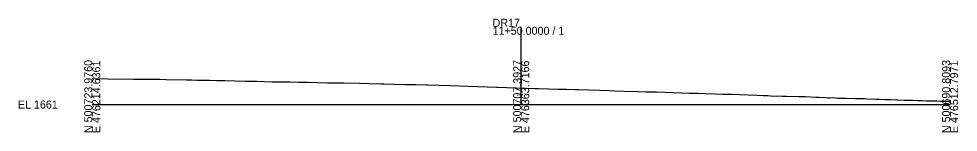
# Model space of a CAD drawing. Extents: x -26 to 303, y -96 to 3030.
# Drawn here: x -25.7 to 302.8, y 2990.3 to 3030 of the extents above; entities that cross this region are included whole.
import ezdxf

# ---------------------------------------------------------------- set-up
doc = ezdxf.new("R2010")
doc.units = 0
for name, color, linetype in [('Exist Cross Section Cell', 7, 'Continuous'), ('Exist XS Center Line Elevation Label', 7, 'Continuous'), ('Exist XS Ground Line', 7, 'Continuous')]:
    doc.layers.add(name, color=color, linetype=linetype)

msp = doc.modelspace()

# ---------------------------------------------------------------- linework, layer by layer
at = {"layer": 'Exist Cross Section Cell'}
for p, q in [((150, 3000), (150, 3027.23)), ((0, 3000), (150, 3000)), ((150, 3000), (300, 3000))]:
    msp.add_line(p, q, dxfattribs=at)
at = {"layer": 'Exist XS Ground Line'}
msp.add_lwpolyline([(0, 3009.08), (5.42, 3009.04), (14.44, 3008.94), (17.43, 3008.89), (18.58, 3008.93), (21.6, 3008.88), (23.69, 3008.84), (25.74, 3008.8), (32.91, 3008.64), (34.73, 3008.61), (36.63, 3008.57), (38.68, 3008.52), (40.97, 3008.48), (43.55, 3008.44), (46.37, 3008.39), (53.54, 3008.2), (57.51, 3008.14), (60.23, 3008.08), (62.98, 3008.01), (65.85, 3007.94), (69.15, 3007.9), (72.13, 3007.84), (75.27, 3007.78), (78.62, 3007.73), (82.26, 3007.66), (84.39, 3007.62), (88.03, 3007.56), (93.43, 3007.44), (97.12, 3007.36), (100.91, 3007.28), (101.96, 3007.26), (105.6, 3007.17), (109.26, 3007.07), (113.01, 3006.97), (116.9, 3006.88), (117.35, 3006.86), (121.31, 3006.76), (125.39, 3006.63), (131.34, 3006.42), (134.85, 3006.29), (138.16, 3006.17), (141.33, 3006.07), (141.73, 3006.05), (144.97, 3005.94), (148.21, 3005.83), (150, 3005.77), (151.53, 3005.72), (154.89, 3005.61), (156.04, 3005.59), (159.56, 3005.48), (162.89, 3005.4), (165.82, 3005.33), (168.84, 3005.27), (170.02, 3005.22), (173.62, 3005.14), (177.4, 3005.04), (180.96, 3004.93), (182.55, 3004.84), (186.05, 3004.72), (190.82, 3004.57), (193.62, 3004.48), (197.32, 3004.42), (200.23, 3004.33), (203.13, 3004.24), (206.07, 3004.14), (208.9, 3004.04), (211.61, 3003.96), (214.34, 3003.87), (217.82, 3003.78), (220.65, 3003.68), (223.5, 3003.59), (226.38, 3003.49), (229.36, 3003.37), (232.38, 3003.24), (234.6, 3003.2), (236.22, 3003.14), (238.09, 3002.97), (239.13, 3003.02), (241.3, 3002.94), (242.81, 3002.92), (247.14, 3002.79), (247.8, 3002.82), (249.29, 3002.76), (253.21, 3002.63), (253.55, 3002.6), (254.22, 3002.54), (256.69, 3002.47), (257.3, 3002.38), (257.97, 3002.37), (258.71, 3002.41), (259.98, 3002.38), (260.77, 3002.25), (262.55, 3002.21), (263.7, 3002.28), (266.92, 3002.17), (270.09, 3002.06), (270.83, 3002.04), (274.29, 3001.91), (274.79, 3001.89), (275.16, 3001.87), (277.22, 3001.81), (279.28, 3001.74), (281.36, 3001.65), (281.74, 3001.63), (284.1, 3001.57), (284.55, 3001.56), (286.97, 3001.48), (288.65, 3001.42), (290.23, 3001.39), (291.8, 3001.35), (292.99, 3001.32), (294.28, 3001.29), (295.34, 3001.26), (296.78, 3001.21), (298.5, 3001.16), (299.3, 3001.14), (300, 3001.12)], dxfattribs=at)

# ---------------------------------------------------------------- texts
at = {"layer": 'Exist Cross Section Cell'}
for s, p in [('DR17', (140, 3027.23)), ('11+50.0000 / 1', (140, 3024.43)), ('EL 1661', (-26, 2998.6))]:
    msp.add_text(s, height=2.8, dxfattribs=at).set_placement(p)
for s, p in [('N 500723.9760', (0, 2990)), ('E 476214.6361', (2.8, 2990)), ('N 500707.3927', (150, 2990)), ('E 476363.7166', (152.8, 2990)), ('N 500690.8093', (300, 2990)), ('E 476512.7971', (302.8, 2990))]:
    msp.add_text(s, height=2.8, rotation=90, dxfattribs=at).set_placement(p)
at = {"layer": 'Exist XS Center Line Elevation Label'}
msp.add_text('1666.77', height=0.75, dxfattribs=at).set_placement((148.33, 3003.02))

doc.saveas('drawing.dxf')
